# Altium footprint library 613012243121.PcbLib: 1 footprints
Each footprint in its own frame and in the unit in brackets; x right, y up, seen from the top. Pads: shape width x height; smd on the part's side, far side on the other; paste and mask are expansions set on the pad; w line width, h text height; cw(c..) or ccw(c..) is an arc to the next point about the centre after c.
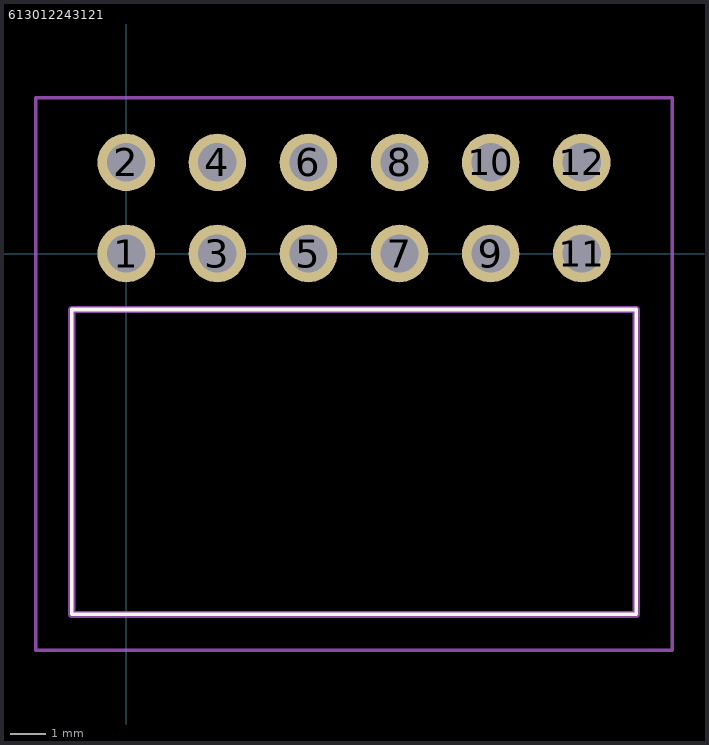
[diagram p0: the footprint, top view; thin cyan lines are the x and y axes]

## 613012243121 [mm]
pads (12):
  round 1.605 hole 1.07: 1(0,0) 2(0,2.54) 3(2.54,0) 4(2.54,2.54) 5(5.08,0) 6(5.08,2.54) 7(7.62,0) 8(7.62,2.54) 9(10.16,0) 10(10.16,2.54) 11(12.7,0) 12(12.7,2.54)
Top Overlay:
  lines w0.1: -1.52,-10.06 14.22,-10.06 14.22,-1.56 -1.52,-1.56 -1.52,-10.06
Mechanical 15:
  lines w0.2: -1.52,-10.06 14.22,-10.06 14.22,-1.56 -1.52,-1.56 -1.52,-10.06
Mechanical 20:
  lines w0.1: -2.52,-11.06 15.22,-11.06 15.22,4.342 -2.52,4.342 -2.52,-11.06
